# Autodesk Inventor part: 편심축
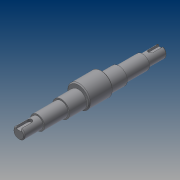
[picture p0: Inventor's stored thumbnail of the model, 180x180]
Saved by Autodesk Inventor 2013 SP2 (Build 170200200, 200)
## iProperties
Created: 2014-12
Part Number: 편심축
Material: Generic
Document SubType Name: Modeling
Designer: CADB202
Density: 1 g/cm^3
Author: CADB202
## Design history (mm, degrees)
sketch "스케치1"
  geometry: L1 (-75.5, 0)-(75.5, 0); L2 (-75.5, 0)-(-75.5, 6); L3 (-75.5, 6)-(-55.5, 6); L4 (-55.5, 6)-(-55.5, 7.5); L5 (-55.5, 7.5)-(-30.5, 7.5); L6 (-30.5, 7.5)-(-30.5, 9); L7 (-30.5, 9)-(30.5, 9); L8 (30.5, 7.5)-(55.5, 7.5); L9 (55.5, 7.5)-(55.5, 6); L10 (55.5, 6)-(75.5, 6); L11 (75.5, 6)-(75.5, 0); L12 (-12.5, 14)-(12.5, 14); L13 (12.5, 14)-(12.5, 2); L14 (12.5, 2)-(-12.5, 2); L15 (-12.5, 2)-(-12.5, 14); L16 (30.5, 7.5)-(30.5, 9); L17 (-75.5, 3)-(-61.5, 3); L18 (-61.5, 3)-(-61.5, 6); L19 (61.5, 6)-(61.5, 3); L20 (61.5, 3)-(75.5, 3); 2 further points
  constraints: 40 end point, 8 parallel, 6 perpendicular, 3 midpoint, 2 collinear, 2 horizontal, 2 point on line, 1 coincident
  dimensions: "d0" = 151 distance of L1.start L1.end; "d2" = 12 diameter of L3 L1; "d3" = 15 diameter of L5 L1; "d4" = 18 diameter of L7 L1; "d5" = 20 distance between parallel lines of L4 L2; "d6" = 25 distance of L4.end L5.end; "d7" = 20 distance of L9.end L10.end; "d8" = 25 distance of L8.start L8.end; "d9" = 2 distance from line of L14 point (0, 0); "d10" = 24 diameter of L12 L14; "d11" = 18 distance between parallel lines of L15 L6; "d12" = 18 distance between parallel lines of L16 L13; "d13" = 12 diameter of L10 L1 (derived); "d14" = 15 diameter of L8 L1 (derived); "d15" = 3 distance between parallel lines of L3 L17; "d16" = 14 distance between parallel lines of L2 L18; "d17" = 3 distance between parallel lines of L10 L20; "d18" = 14 distance between parallel lines of L11 L19
revolve "회전1" stored, may be unused: angle "d19" = 90 deg
revolve "회전2" stored, may be unused: angle "d20" = 90 deg
extrude "돌출1" cut sketch "스케치1" stored distance "d21" = 5; taper "d22" = 0 deg
extrude "돌출2" cut sketch "스케치1" stored distance "d23" = 5; taper "d24" = 0 deg
chamfer "모따기1" distance "d25" = 1; stored, may be unused: second distance "d26" = 2, angle "d27" = 45 deg
fillet "모깎기1" dims "d28" = 2.5
node "솔리드1"
